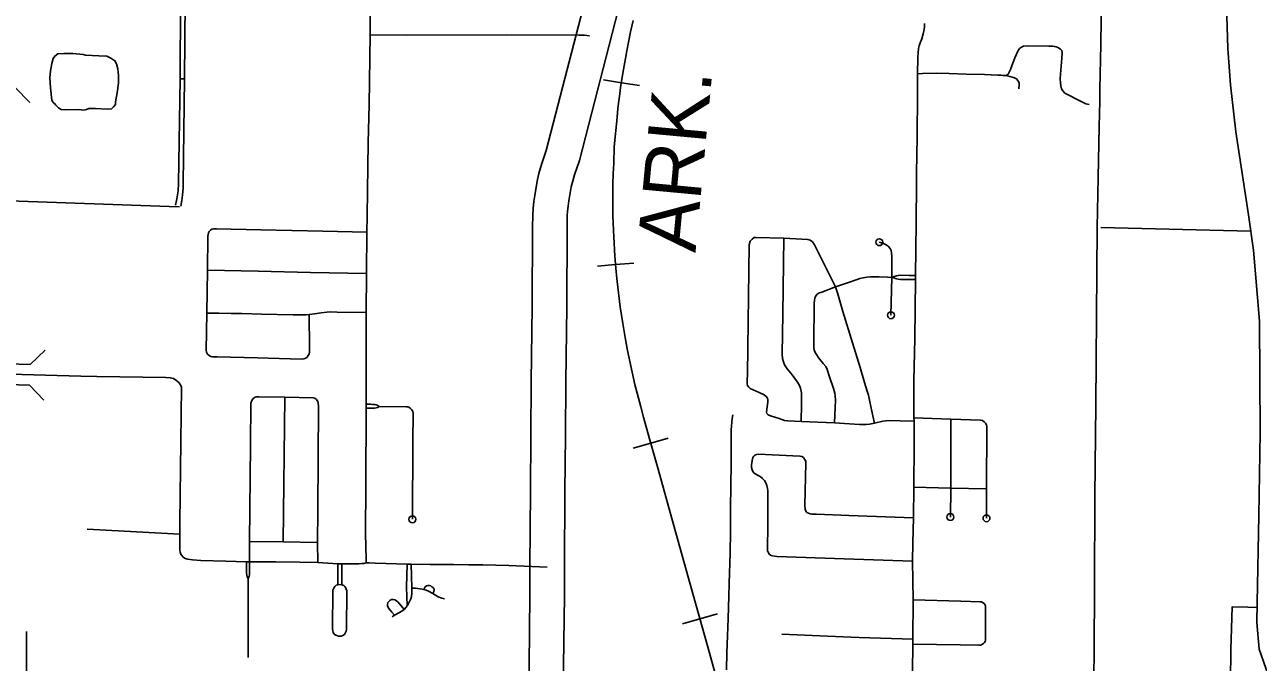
# Model space of a CAD drawing. Extents: x 670147 to 673275, y 705573 to 707613.
# Drawn here: x 671751.4 to 671930, y 706370.5 to 706462.8 of the extents above; entities that cross this region are included whole.
import ezdxf

# ---------------------------------------------------------------- set-up
doc = ezdxf.new("R2010")
doc.units = 0
for name, color, linetype in [('10', 7, 'Continuous'), ('15', 7, 'Continuous'), ('33', 7, 'Continuous'), ('34', 7, 'Continuous'), ('35', 7, 'Continuous'), ('39', 7, 'Continuous'), ('4', 7, 'Continuous'), ('40', 7, 'Continuous'), ('6', 7, 'Continuous')]:
    doc.layers.add(name, color=color, linetype=linetype)

msp = doc.modelspace()

# ---------------------------------------------------------------- linework, layer by layer
at = {"layer": '10'}
msp.add_lwpolyline([(671948.19, 706298.41), (671943.2, 706298.13), (671942.65, 706307.69), (671942.07, 706322.94), (671940.76, 706333.16), (671939.34, 706342.48), (671937.73, 706350.91), (671936.4, 706355.25), (671932.65, 706365.12), (671930.1, 706372.43), (671929.76, 706376.28), (671929.8, 706379.12), (671930.02, 706391.79), (671930.22, 706403.72), (671930.13, 706419.92), (671929.25, 706430.18), (671928.54, 706435.29), (671926.7, 706447.29), (671925.93, 706454.11), (671925.54, 706459.35), (671925.29, 706467.16), (671925.17, 706486.12), (671925.16, 706488.79)], dxfattribs=at)
at = {"layer": '15'}
for points in [[(671824.93, 706433.41), (671824.96, 706435.3), (671825, 706436.22), (671825.12, 706437.23), (671825.25, 706438.1), (671825.45, 706439.31), (671825.64, 706440.38), (671825.86, 706441.29), (671826.23, 706442.57), (671826.9, 706444.59), (671832.92, 706467.92)], [(671837.75, 706466.63), (671831.7, 706443.17), (671831.01, 706441.09), (671830.7, 706440.01), (671830.54, 706439.35), (671830.38, 706438.47), (671830.19, 706437.32), (671830.08, 706436.56), (671829.99, 706435.81), (671829.96, 706435.14), (671829.93, 706433.33)], [(671829.13, 706331.23), (671824.13, 706331.36), (671824.19, 706337.01), (671824.19, 706347.17), (671824.33, 706357.67), (671824.34, 706358.49), (671824.43, 706370.07), (671824.53, 706380.21), (671824.55, 706384.32), (671824.62, 706395.26), (671824.68, 706403.35), (671824.75, 706411.17), (671824.87, 706422.02), (671824.93, 706433.41)], [(671829.93, 706433.33), (671829.87, 706421.98), (671829.75, 706411.12), (671829.68, 706403.31), (671829.62, 706395.23), (671829.55, 706384.29), (671829.53, 706380.18), (671829.43, 706370.03), (671829.34, 706358.43), (671829.32, 706357.59), (671829.19, 706347.14), (671829.19, 706336.98), (671829.13, 706331.23)]]:
    msp.add_lwpolyline(points, dxfattribs=at)
at = {"layer": '33'}
for points in [[(671801.44, 706461.36), (671801.49, 706469.25), (671801.68, 706480.81), (671801.88, 706495.12), (671801.98, 706503.42), (671802.12, 706513.06), (671802.27, 706522.36), (671802.36, 706529.19), (671802.53, 706541.33)], [(671773.26, 706436.69), (671773.47, 706437.59), (671773.64, 706438.77), (671773.69, 706439.83), (671773.91, 706454.97), (671773.99, 706466.2), (671774.08, 706475.81), (671774.37, 706487.56), (671774.42, 706490.97), (671774.56, 706497.07)], [(671774.04, 706436.52), (671774.18, 706437.35), (671774.29, 706438.14), (671774.38, 706439.22), (671774.35, 706439.82), (671774.57, 706454.96), (671774.68, 706466.2), (671774.74, 706475.81), (671775.01, 706487.55), (671775.09, 706490.97), (671775.14, 706497.2)], [(671881.24, 706460.78), (671881.44, 706461.47), (671881.6, 706462.09), (671881.66, 706462.55), (671881.67, 706462.98)], [(671800.84, 706384.9), (671800.85, 706385.47), (671800.77, 706389.16), (671800.79, 706396.07), (671800.84, 706407.3), (671800.84, 706407.91), (671800.84, 706415.59), (671800.86, 706421.15), (671800.91, 706426.79), (671800.93, 706432.77), (671800.98, 706435.12), (671801.06, 706438.75), (671801.11, 706442.28), (671801.14, 706445.72), (671801.28, 706451.25), (671801.44, 706461.36)], [(671833.19, 706461.2), (671832.46, 706461.28), (671831.69, 706461.28), (671821.15, 706461.32), (671806.62, 706461.31), (671801.44, 706461.36)], [(671879.85, 706365.25), (671879.97, 706373.13), (671879.95, 706373.87), (671880, 706379.59), (671879.91, 706385.15), (671879.98, 706387.84), (671880.04, 706391.42), (671880.09, 706395.88), (671880.17, 706402.05), (671880.14, 706405.42), (671880.12, 706405.9), (671880.11, 706408.77), (671880.13, 706411.24), (671880.27, 706417.4), (671880.33, 706425.95), (671880.35, 706426.5), (671880.42, 706434.12), (671880.48, 706439.88), (671880.5, 706441.31), (671880.6, 706446.56), (671880.64, 706452.75), (671880.65, 706455.72), (671880.67, 706458.06), (671880.71, 706458.75), (671880.79, 706459.34), (671880.89, 706459.75), (671881.01, 706460.17), (671881.24, 706460.78)], [(671773.91, 706454.97), (671774.57, 706454.96)], [(671800.93, 706432.77), (671794.59, 706432.91), (671785.59, 706433.12), (671779.19, 706433.28), (671778.76, 706433.27), (671778.5, 706433.2), (671778.33, 706433.08), (671778.13, 706432.9), (671778.02, 706432.68), (671777.97, 706432.45), (671777.96, 706432.2), (671777.91, 706427.26), (671777.81, 706421.06), (671777.7, 706415.68), (671777.74, 706415.41), (671777.9, 706415.13), (671778.11, 706414.92), (671778.38, 706414.77), (671778.63, 706414.73), (671779.29, 706414.72), (671785.11, 706414.58), (671791.45, 706414.42), (671791.83, 706414.44), (671792.12, 706414.53), (671792.31, 706414.7), (671792.47, 706414.91), (671792.59, 706415.17), (671792.64, 706415.42), (671792.63, 706416.03), (671792.59, 706420.86)], [(671880.14, 706405.42), (671878.11, 706405.49), (671876.59, 706405.53), (671876.07, 706405.49), (671875.62, 706405.43), (671874.41, 706405.16), (671873.68, 706405), (671873.23, 706404.95), (671872.24, 706404.95), (671868.64, 706405.17), (671863.78, 706405.38), (671861.85, 706405.46), (671861.4, 706405.53), (671860.6, 706405.79), (671859.38, 706406.18), (671859.03, 706406.35), (671858.84, 706406.54), (671858.79, 706406.71), (671858.82, 706407.15), (671858.99, 706408.2), (671858.99, 706408.5), (671858.93, 706408.76), (671858.75, 706409), (671858.45, 706409.23), (671857.72, 706409.58), (671856.41, 706410.16), (671856.22, 706410.35), (671856.04, 706410.61), (671856, 706410.78), (671856, 706411.28), (671856.02, 706412.29), (671856.28, 706430.97), (671856.41, 706431.47), (671856.69, 706431.79), (671856.99, 706431.99), (671857.29, 706432.03), (671861.27, 706431.9), (671864.75, 706431.73), (671865.1, 706431.6), (671865.44, 706431.36), (671865.72, 706430.93), (671868.76, 706424.86)], [(671861.27, 706431.9), (671861.14, 706420.95), (671861.03, 706415.12), (671861.1, 706414.52), (671861.23, 706414.02), (671861.4, 706413.59), (671861.78, 706413.01), (671862.49, 706412.11), (671863.27, 706411.07), (671863.55, 706410.6), (671863.72, 706410.19), (671863.83, 706409.52), (671863.85, 706408.9), (671863.83, 706407.91), (671863.78, 706405.38)], [(671875.11, 706431.33), (671875.42, 706431.26), (671875.74, 706431.15), (671876.11, 706430.97), (671876.41, 706430.75), (671876.7, 706430.44), (671876.83, 706430.12), (671876.89, 706429.79), (671876.93, 706429.26), (671876.93, 706426.23), (671876.8, 706420.76)], [(671777.91, 706427.26), (671785.21, 706427.12), (671792.8, 706426.95), (671800.91, 706426.79)], [(671876.93, 706426.23), (671877.28, 706426.36), (671877.62, 706426.47), (671877.87, 706426.52), (671878.24, 706426.55), (671879.41, 706426.52), (671880.35, 706426.5)], [(671868.64, 706405.17), (671868.74, 706407.42), (671868.75, 706408.46), (671868.73, 706409.08), (671868.67, 706409.49), (671868.46, 706410.15), (671867.92, 706411.85), (671867.57, 706412.91), (671867.35, 706413.32), (671866.98, 706413.78), (671866.37, 706414.55), (671865.91, 706415.21), (671865.79, 706415.46), (671865.67, 706415.75), (671865.64, 706416.08), (671865.64, 706416.64), (671865.7, 706422.51), (671865.78, 706423.26), (671865.86, 706423.49), (671866.05, 706423.74), (671866.29, 706423.93), (671866.79, 706424.12), (671868.76, 706424.86), (671870.49, 706425.47), (671871.9, 706425.95), (671872.27, 706426.08), (671872.73, 706426.16), (671873.29, 706426.26), (671873.84, 706426.3), (671875.07, 706426.3), (671876.28, 706426.26), (671876.93, 706426.23)], [(671868.76, 706424.86), (671869.05, 706423.99), (671869.85, 706421.3), (671871.24, 706416.77), (671872.32, 706413.19), (671872.97, 706411.04), (671873.35, 706409.78), (671873.54, 706409.19), (671873.73, 706408.23), (671874.17, 706406.2), (671874.41, 706405.16)], [(671876.93, 706426.23), (671877.22, 706426.15), (671877.44, 706426.07), (671877.63, 706426.01), (671877.85, 706425.96), (671878.2, 706425.95), (671880.33, 706425.95)], [(671800.86, 706421.15), (671796.64, 706421.22), (671795.65, 706421.24), (671795.14, 706421.19), (671794.35, 706421.1), (671793.35, 706420.98), (671792.59, 706420.86), (671792.15, 706420.82), (671791.51, 706420.8), (671790.3, 706420.82), (671785.69, 706420.92), (671782.85, 706420.99), (671781.3, 706421.03), (671779.53, 706421.07), (671777.81, 706421.06)], [(671744.18, 706412.38), (671759.55, 706411.93), (671761.89, 706411.91), (671771.88, 706411.77), (671772.49, 706411.7), (671772.95, 706411.58), (671773.43, 706411.28), (671773.78, 706410.96), (671774.04, 706410.61), (671774.11, 706410.33), (671774.01, 706402.42), (671773.89, 706390.74), (671773.88, 706389.08), (671773.87, 706386.77), (671773.91, 706386.45), (671774.05, 706386.17), (671774.34, 706385.79), (671774.58, 706385.59), (671774.8, 706385.5), (671775.04, 706385.44), (671775.38, 706385.39), (671775.72, 706385.36), (671776.92, 706385.28), (671780.56, 706385.15), (671783.51, 706385.07), (671783.99, 706385.07), (671787.79, 706385.06), (671791.2, 706385.01), (671793.84, 706384.96)], [(671783.99, 706385.07), (671783.99, 706388.02), (671784.12, 706401.97), (671784.18, 706408.05), (671784.29, 706408.44), (671784.52, 706408.7), (671784.79, 706408.88), (671784.96, 706408.94), (671785.32, 706408.94), (671789.06, 706408.88), (671793.25, 706408.8), (671793.44, 706408.74), (671793.65, 706408.56), (671793.84, 706408.27), (671793.89, 706408.03), (671793.95, 706407.58), (671793.87, 706392.52), (671793.81, 706387.88), (671793.84, 706384.96)], [(671788.86, 706387.95), (671789.06, 706408.88)], [(671800.84, 706407.91), (671801.16, 706407.89), (671801.49, 706407.87), (671801.75, 706407.86), (671801.99, 706407.85), (671802.12, 706407.83), (671802.31, 706407.77), (671802.44, 706407.72), (671802.71, 706407.56), (671802.47, 706407.42), (671802.32, 706407.37), (671802.06, 706407.33), (671801.66, 706407.3), (671800.84, 706407.3)], [(671807.54, 706391.22), (671807.62, 706402.5), (671807.66, 706406.56), (671807.61, 706406.83), (671807.44, 706407.09), (671807.27, 706407.27), (671807.04, 706407.43), (671806.88, 706407.49), (671806.62, 706407.52), (671802.71, 706407.56)], [(671853.02, 706369.45), (671853.06, 706371.89), (671853.13, 706374.35), (671853.22, 706376.86), (671853.35, 706380.12), (671853.36, 706381.91), (671853.52, 706386.39), (671853.56, 706389.44), (671853.58, 706392.67), (671853.61, 706396.17), (671853.68, 706399.18), (671853.68, 706404.19), (671853.8, 706405.79), (671853.9, 706406.36)], [(671880.12, 706405.9), (671885.46, 706405.71), (671889.74, 706405.58), (671890.03, 706405.51), (671890.29, 706405.34), (671890.49, 706405.15), (671890.63, 706404.91), (671890.67, 706404.64), (671890.63, 706395.63), (671890.62, 706391.38)], [(671885.39, 706391.55), (671885.46, 706395.74), (671885.46, 706405.71)], [(671879.91, 706385.15), (671870.02, 706385.51), (671860.26, 706385.86), (671859.67, 706385.92), (671859.47, 706385.97), (671859.24, 706386.14), (671859.07, 706386.36), (671858.95, 706386.65), (671858.93, 706386.89), (671858.96, 706390.4), (671858.96, 706395.37), (671858.94, 706395.69), (671858.85, 706396.13), (671858.69, 706396.48), (671858.49, 706396.85), (671858.2, 706397.14), (671857.88, 706397.41), (671857.58, 706397.57), (671857.15, 706397.79), (671856.96, 706397.94), (671856.82, 706398.13), (671856.7, 706398.39), (671856.63, 706398.71), (671856.63, 706399.12), (671856.7, 706399.72), (671856.83, 706400.18), (671856.95, 706400.35), (671857.12, 706400.49), (671857.36, 706400.62), (671857.62, 706400.66), (671863.61, 706400.38), (671863.88, 706400.3), (671864.12, 706400.15), (671864.3, 706399.95), (671864.4, 706399.8), (671864.46, 706399.62), (671864.5, 706399.38), (671864.33, 706393.22), (671864.37, 706392.67), (671864.47, 706392.41), (671864.64, 706392.23), (671864.86, 706392.09), (671865.1, 706392.02), (671865.33, 706391.98), (671866.02, 706391.97), (671870.69, 706391.79), (671880.04, 706391.42)], [(671880.09, 706395.88), (671885.46, 706395.74), (671890.63, 706395.63)], [(671760.48, 706389.8), (671773.88, 706389.08)], [(671783.99, 706388.02), (671788.86, 706387.95), (671793.81, 706387.88)], [(671783.99, 706385.07), (671783.99, 706383.53), (671783.99, 706383.21), (671783.92, 706382.98), (671783.76, 706382.59), (671783.64, 706382.9), (671783.58, 706383.16), (671783.52, 706383.53), (671783.52, 706384.04), (671783.51, 706385.07)], [(671793.84, 706384.96), (671796.75, 706384.8), (671797.34, 706384.79), (671799.33, 706384.77), (671799.81, 706384.79), (671800.2, 706384.81), (671800.49, 706384.85), (671800.84, 706384.9), (671801.29, 706384.92), (671802.16, 706384.87), (671806.77, 706384.75), (671807.37, 706384.74), (671810.11, 706384.69), (671813.47, 706384.68), (671815.69, 706384.65), (671817.74, 706384.65), (671821.48, 706384.56), (671827.05, 706384.3)], [(671796.75, 706384.8), (671796.75, 706381.76)], [(671797.34, 706384.79), (671797.34, 706381.76)], [(671806.77, 706384.75), (671806.7, 706381.42), (671806.77, 706378.72), (671806.64, 706378.51), (671806.36, 706378.19), (671806, 706377.91), (671805.13, 706377.45), (671804.94, 706377.37), (671804.61, 706377.1)], [(671806.77, 706378.72), (671807.03, 706379.12), (671807.19, 706379.4), (671807.33, 706379.71), (671807.39, 706380.06), (671807.44, 706380.47), (671807.46, 706381.27), (671807.37, 706384.74)], [(671783.76, 706382.59), (671783.76, 706371.24)], [(671797.34, 706381.76), (671797.6, 706381.62), (671797.75, 706381.51), (671797.88, 706381.34), (671797.96, 706381.13), (671798.03, 706380.88), (671798, 706375.27), (671797.96, 706375.02), (671797.87, 706374.82), (671797.7, 706374.57), (671797.46, 706374.39), (671797.21, 706374.32), (671797.05, 706374.31), (671796.83, 706374.33), (671796.62, 706374.4), (671796.45, 706374.47), (671796.29, 706374.57), (671796.16, 706374.71), (671796.09, 706374.84), (671796.03, 706375.13), (671796, 706375.35), (671796.03, 706380.95), (671796.15, 706381.28), (671796.32, 706381.51), (671796.53, 706381.68), (671796.75, 706381.76), (671797.04, 706381.78), (671797.34, 706381.76)], [(671807.46, 706381.27), (671807.71, 706381.27), (671807.97, 706381.26), (671808.3, 706381.21), (671808.66, 706381.14), (671808.95, 706381.11), (671809.21, 706381.05), (671809.55, 706380.97), (671809.88, 706380.8), (671810.52, 706380.47), (671811.26, 706380.02), (671811.79, 706379.8), (671812.21, 706379.69)], [(671809.21, 706381.05), (671809.28, 706381.26), (671809.41, 706381.46), (671809.6, 706381.59), (671809.8, 706381.65), (671810.02, 706381.63), (671810.19, 706381.57), (671810.37, 706381.46), (671810.62, 706381.24), (671810.67, 706381.01), (671810.64, 706380.76), (671810.52, 706380.47)], [(671804.94, 706377.37), (671804.57, 706377.8), (671804.14, 706378.33), (671803.95, 706378.65), (671803.92, 706378.9), (671803.99, 706379.17), (671804.13, 706379.35), (671804.33, 706379.51), (671804.5, 706379.6), (671804.75, 706379.62), (671805, 706379.55), (671805.22, 706379.43), (671805.46, 706379.23), (671806.36, 706378.19)], [(671880, 706379.59), (671886.9, 706379.39), (671889.69, 706379.3), (671889.9, 706379.26), (671890.13, 706379.15), (671890.31, 706378.99), (671890.43, 706378.81), (671890.47, 706378.67), (671890.48, 706378.43), (671890.48, 706373.99), (671890.48, 706373.75), (671890.43, 706373.55), (671890.33, 706373.4), (671890.19, 706373.24), (671889.95, 706373.08), (671889.79, 706373.02), (671889.49, 706373.01), (671886.79, 706373.05), (671879.97, 706373.13)], [(671752.94, 706353.85), (671752.36, 706355.95), (671751.86, 706359.21), (671751.8, 706361.95), (671751.7, 706363.08), (671751.68, 706363.99), (671751.7, 706365.38), (671751.7, 706374.97)], [(671861, 706374.59), (671867.6, 706374.32), (671872.19, 706374.14), (671879.95, 706373.87)]]:
    msp.add_lwpolyline(points, dxfattribs=at)
for centre in [(671875.11, 706431.33), (671876.8, 706420.76), (671807.54, 706391.22), (671885.39, 706391.55), (671890.62, 706391.38)]:
    msp.add_circle(centre, 0.5, dxfattribs=at)
at = {"layer": '34'}
for points in [[(671905.46, 706451.24), (671905.01, 706451.35), (671903.93, 706451.89), (671902.32, 706452.69), (671901.98, 706452.91), (671901.67, 706453.24), (671901.49, 706453.54), (671901.39, 706453.98), (671901.32, 706454.37), (671901.28, 706454.98), (671901.31, 706455.64), (671901.5, 706457.96), (671901.59, 706458.67), (671901.59, 706458.81), (671901.5, 706459.05), (671901.31, 706459.25), (671900.95, 706459.5), (671900.71, 706459.61), (671900.48, 706459.67), (671900.23, 706459.71), (671899.62, 706459.72), (671896.59, 706459.74), (671895.97, 706459.68), (671895.7, 706459.57), (671895.41, 706459.36), (671895.15, 706459), (671894.71, 706458.02), (671894.1, 706456.31), (671893.75, 706455.65), (671893.45, 706455.45)], [(671895.32, 706453.54), (671895.34, 706454.13), (671895.33, 706454.34), (671895.24, 706454.57), (671895.12, 706454.76), (671894.94, 706454.96), (671894.65, 706455.13), (671894.35, 706455.22), (671894, 706455.31), (671893.65, 706455.39), (671893.31, 706455.45), (671893, 706455.47), (671892.68, 706455.49), (671892.24, 706455.5), (671890.34, 706455.58), (671887.69, 706455.67), (671885.2, 706455.76), (671883.35, 706455.78), (671881.35, 706455.75), (671880.65, 706455.72)]]:
    msp.add_lwpolyline(points, dxfattribs=at)
at = {"layer": '35'}
for points in [[(671759.22, 706450.52), (671757.33, 706450.49), (671756.71, 706450.54), (671756.33, 706450.78), (671755.95, 706451.16), (671755.75, 706451.38), (671755.57, 706451.56), (671755.37, 706451.89), (671755.17, 706453.69), (671755.08, 706455.14), (671755.17, 706456.14), (671755.37, 706457.18), (671755.55, 706457.92), (671755.79, 706458.27), (671756.24, 706458.58), (671757.08, 706458.65), (671758.39, 706458.63), (671759.9, 706458.47), (671760.22, 706458.41)], [(671760.22, 706458.41), (671761.19, 706458.34), (671762.15, 706458.32), (671763.33, 706458.23), (671763.9, 706457.94), (671764.48, 706457.58), (671764.73, 706457.12), (671764.9, 706456.41), (671764.99, 706455.47), (671765.01, 706454.34), (671764.84, 706452.94), (671764.59, 706451.63), (671764.59, 706451.27), (671764.3, 706450.92), (671763.99, 706450.63), (671763.37, 706450.58), (671761.68, 706450.67), (671760.73, 706450.69), (671760.39, 706450.52), (671759.99, 706450.43), (671759.22, 706450.52)]]:
    msp.add_lwpolyline(points, dxfattribs=at)
at = {"layer": '39'}
for p, q in [((671750.06, 706453.7), (671752.17, 706451.57)), ((671741.69, 706413.95), (671752.24, 706413.63)), ((671741.59, 706410.96), (671752.15, 706410.63))]:
    msp.add_line(p, q, dxfattribs=at)
for points in [[(671752.24, 706413.63), (671754.42, 706415.69)], [(671754.21, 706408.45), (671752.15, 706410.63)]]:
    msp.add_lwpolyline(points, dxfattribs=at)
at = {"layer": '4'}
msp.add_lwpolyline([(671928.87, 706432.92), (671907.17, 706433.47)], dxfattribs=at)
at = {"layer": '40'}
for p, q in [((671837.79, 706454.41), (671835.18, 706454.81)), ((671837.79, 706454.41), (671840.4, 706454.01)), ((671836.95, 706428.09), (671839.58, 706428.3)), ((671836.95, 706428.09), (671834.32, 706427.87)), ((671842.03, 706402.23), (671839.49, 706401.51)), ((671842.03, 706402.23), (671844.57, 706402.95)), ((671849.15, 706376.81), (671846.61, 706376.1)), ((671849.15, 706376.81), (671851.69, 706377.52))]:
    msp.add_line(p, q, dxfattribs=at)
for points in [[(671852.22, 706365.78), (671850.24, 706372.9), (671847.75, 706381.83), (671845.08, 706391.33), (671843.09, 706398.47), (671841.84, 706402.88), (671840.99, 706406.02), (671840.58, 706407.49), (671839.72, 706410.71), (671838.96, 706414.32), (671838.64, 706415.91), (671838.33, 706417.55), (671837.99, 706419.56), (671837.62, 706421.97), (671837.18, 706425.62), (671837.03, 706427.05), (671836.85, 706429.31), (671836.69, 706432.12), (671836.64, 706433.04), (671836.58, 706434.18), (671836.56, 706435.08), (671836.53, 706436.91), (671836.55, 706438.73), (671836.56, 706439.72), (671836.59, 706441.23), (671836.67, 706442.78), (671836.76, 706445.07), (671836.89, 706446.59), (671837.02, 706447.92), (671837.17, 706449.41), (671837.29, 706450.67), (671837.43, 706451.81), (671837.54, 706452.79), (671837.68, 706453.71), (671837.86, 706454.91), (671838.08, 706456.32), (671838.37, 706457.9), (671838.56, 706459.02), (671838.83, 706460.28), (671839.12, 706461.76), (671839.48, 706463.4)], [(671839.48, 706463.4), (671839.12, 706461.76), (671838.83, 706460.28), (671838.56, 706459.02), (671838.37, 706457.9), (671838.08, 706456.32), (671837.86, 706454.91), (671837.68, 706453.71), (671837.54, 706452.79), (671837.43, 706451.81), (671837.29, 706450.67), (671837.17, 706449.41), (671837.02, 706447.92), (671836.89, 706446.59), (671836.76, 706445.07), (671836.67, 706442.78), (671836.59, 706441.23), (671836.56, 706439.72), (671836.55, 706438.73), (671836.53, 706436.91), (671836.56, 706435.08), (671836.58, 706434.18), (671836.64, 706433.04), (671836.69, 706432.12), (671836.85, 706429.31), (671837.03, 706427.05), (671837.18, 706425.62), (671837.62, 706421.97), (671837.99, 706419.56), (671838.33, 706417.55), (671838.64, 706415.91), (671838.96, 706414.32), (671839.72, 706410.71), (671840.58, 706407.49), (671840.99, 706406.02), (671841.84, 706402.88), (671843.09, 706398.47), (671845.08, 706391.33), (671847.75, 706381.83), (671850.24, 706372.9), (671852.22, 706365.78)]]:
    msp.add_lwpolyline(points, dxfattribs=at)
at = {"layer": '6'}
for points in [[(671907.5, 706485.1), (671907.16, 706459.92), (671907.04, 706453.5), (671907, 706451.76), (671906.93, 706448.09), (671906.78, 706440.69), (671906.64, 706433.47), (671906.43, 706407.74), (671906.31, 706394.57), (671906.24, 706381.46), (671906.18, 706372.22), (671906.16, 706368.39), (671908.37, 706368.32), (671910.58, 706368.24), (671912.58, 706368.16), (671914.56, 706368.09), (671916.43, 706368.02), (671919.36, 706367.91), (671920.93, 706367.97), (671920.82, 706361.07), (671920.74, 706355.02)], [(671733.4, 706412.84), (671733.41, 706413.26), (671733.42, 706414.35), (671733.69, 706437.47), (671743.25, 706437.41), (671747.63, 706437.38), (671748.88, 706437.34), (671749.24, 706437.32), (671772.33, 706436.5), (671773.82, 706436.44)], [(671925.86, 706354.86), (671925.95, 706367.79), (671925.99, 706372.35), (671926.19, 706378.56), (671928.44, 706378.53), (671929.79, 706378.46)]]:
    msp.add_lwpolyline(points, dxfattribs=at)

# ---------------------------------------------------------------- texts
at = {"layer": '40'}
msp.add_text('ARK.', height=8.448, rotation=84.6797, dxfattribs=at).set_placement((671848.5, 706429.73))

doc.saveas('drawing.dxf')
